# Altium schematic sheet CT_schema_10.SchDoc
size 387 x 385 mm
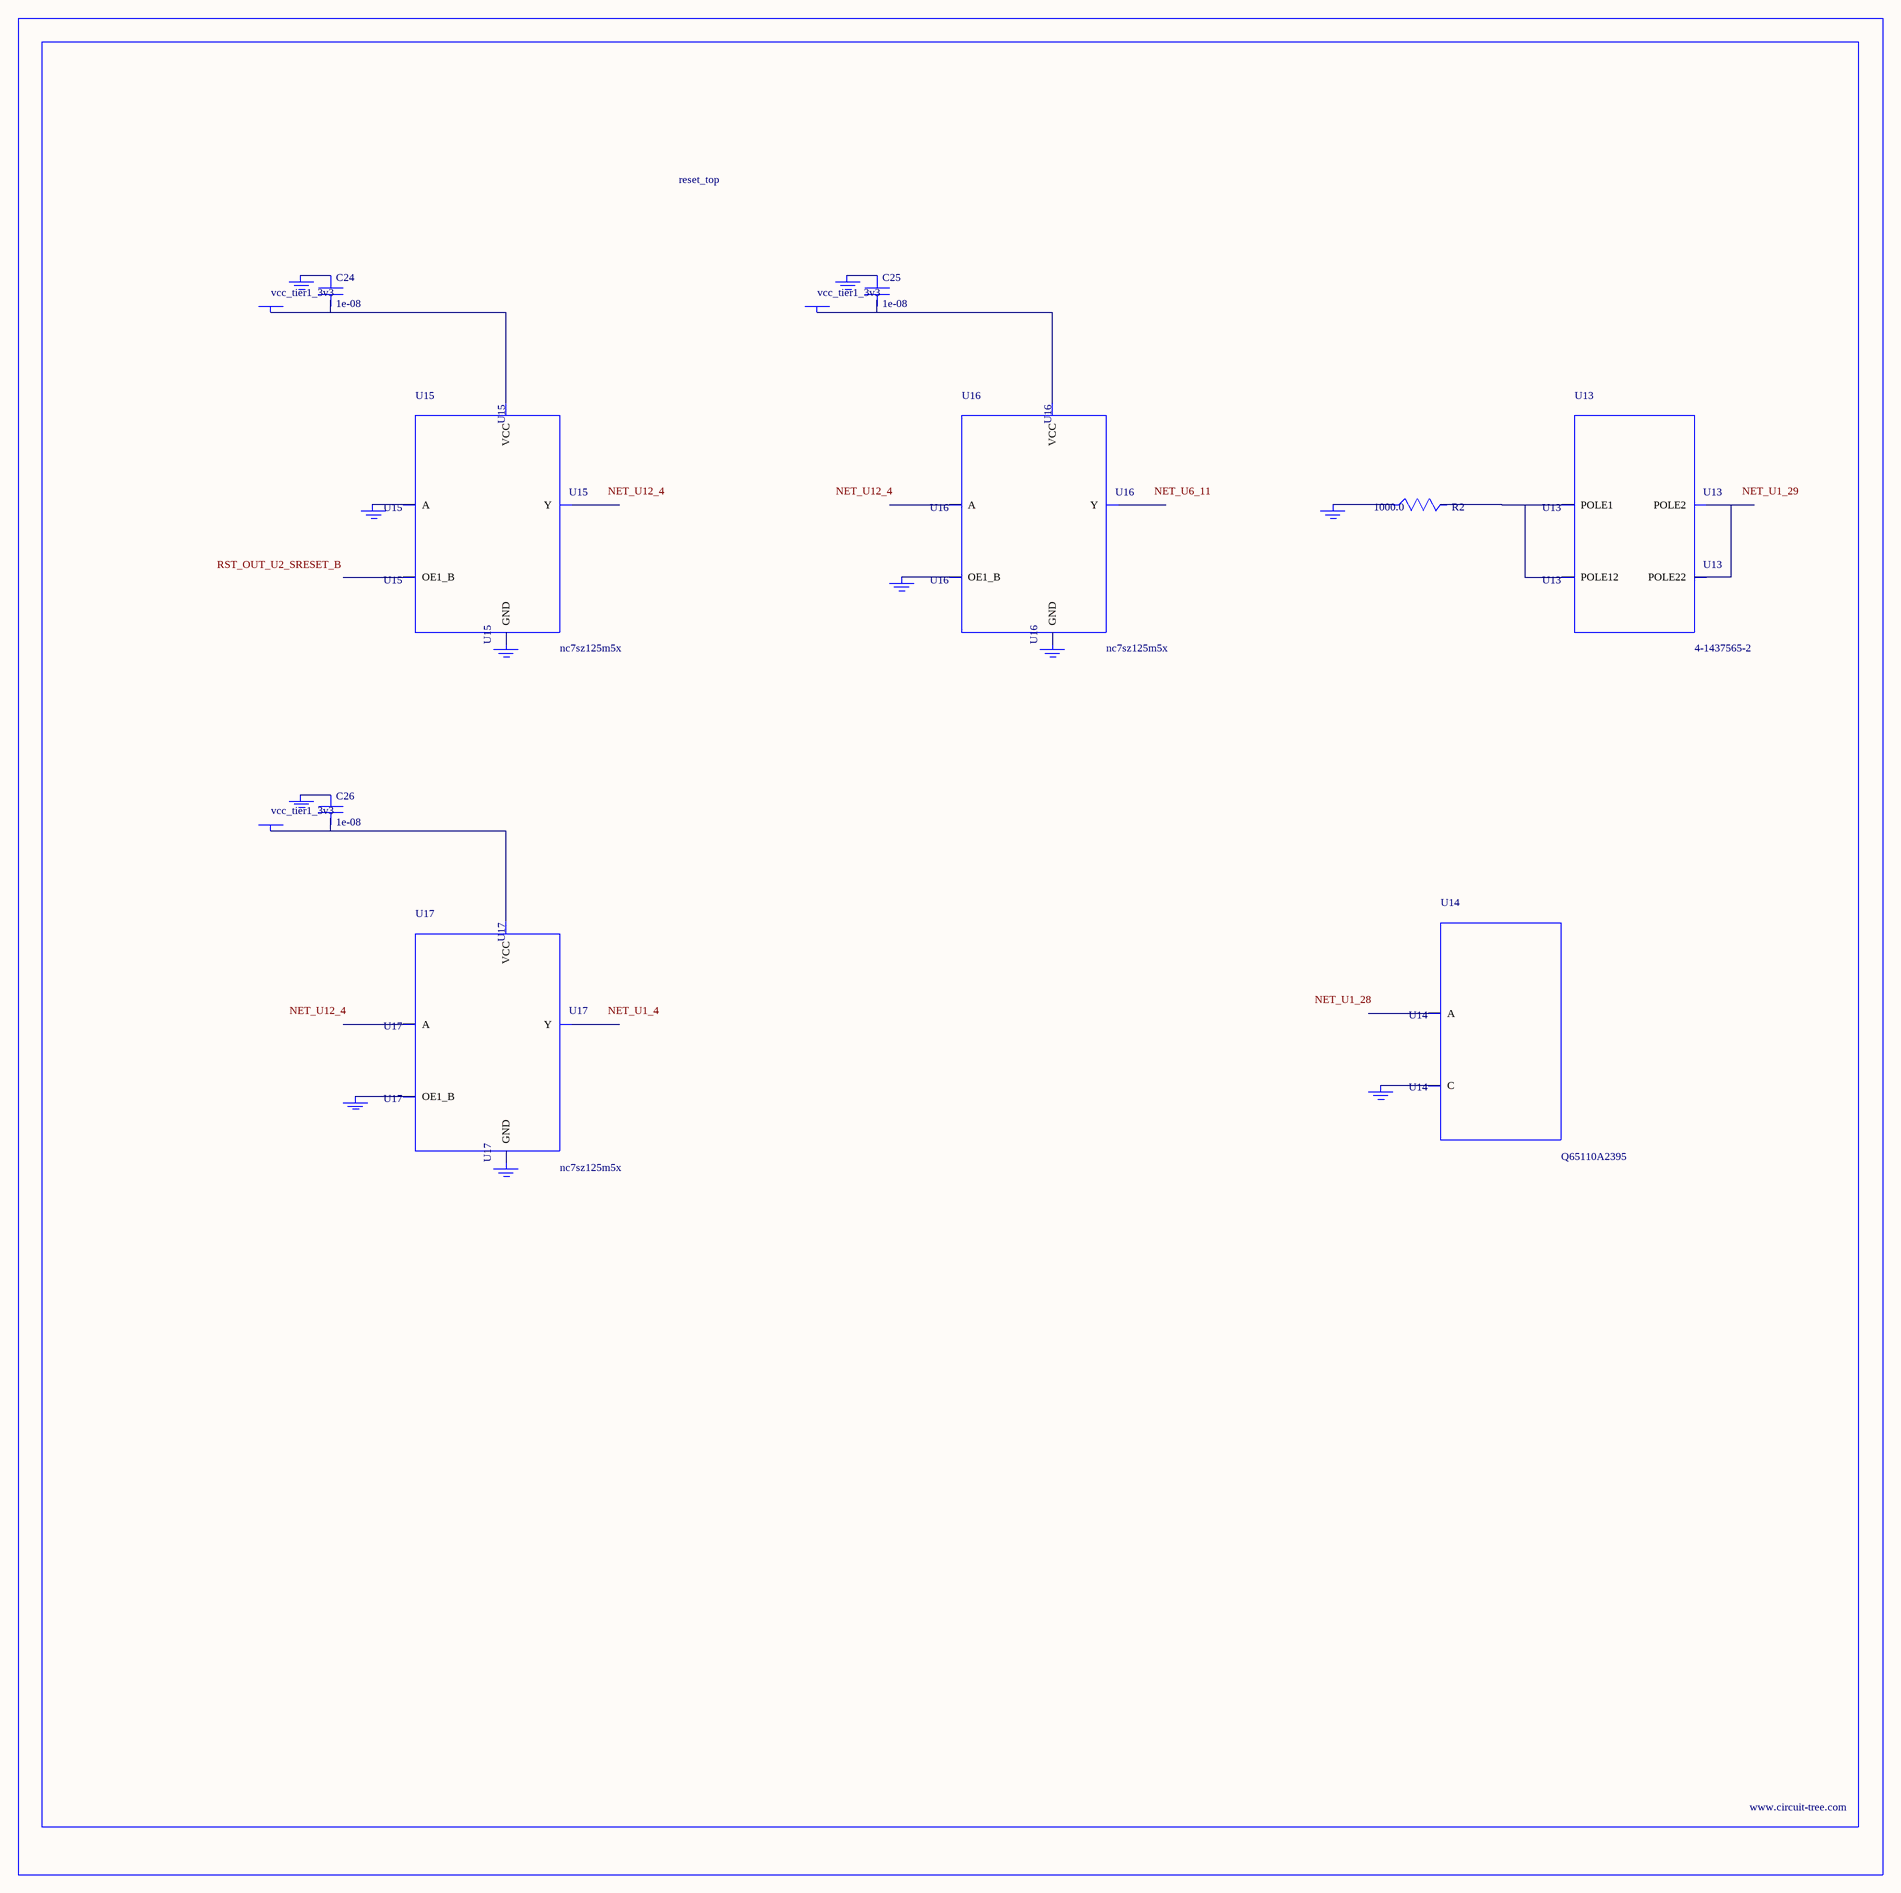
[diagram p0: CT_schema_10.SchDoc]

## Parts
BORDER9  (no value)
C24  1e-08  [C0402]
C25  1e-08  [C0402]
C26  1e-08  [C0402]
GND_INSTANCE_9_0  (no value)
GND_INSTANCE_9_1  (no value)
GND_INSTANCE_9_2  (no value)
GND_INSTANCE_9_3  (no value)
GND_INSTANCE_9_4  (no value)
GND_INSTANCE_9_5  (no value)
GND_INSTANCE_9_6  (no value)
GND_INSTANCE_9_7  (no value)
GND_INSTANCE_9_8  (no value)
GND_INSTANCE_9_9  (no value)
GND_INSTANCE_9_10  (no value)
POWER_INSTANCE_9_0  vcc_tier1_3v3
POWER_INSTANCE_9_1  vcc_tier1_3v3
POWER_INSTANCE_9_2  vcc_tier1_3v3
R2  1000.0  [R0603]
U13  4-1437565-2  [SW_4-1437565-2]
U14  Q65110A2395  [LGM67K-G1J2-24-Z]
U15  nc7sz125m5x  [NC7SZ125M5X]
U16  nc7sz125m5x  [NC7SZ125M5X]
U17  nc7sz125m5x  [NC7SZ125M5X]

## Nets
NetC24_1: C24.1 GND_INSTANCE_9_2.0(GND)
NetC24_2: C24.2 POWER_INSTANCE_9_0.0(PWR) U15.5(VCC)
NetC25_1: C25.1 GND_INSTANCE_9_5.0(GND)
NetC25_2: C25.2 POWER_INSTANCE_9_1.0(PWR) U16.5(VCC)
NetC26_1: C26.1 GND_INSTANCE_9_8.0(GND)
NetC26_2: C26.2 POWER_INSTANCE_9_2.0(PWR) U17.5(VCC)
NetGND_INSTANCE_9_0_0: GND_INSTANCE_9_0.0(GND) R2.1
NetGND_INSTANCE_9_1_0: GND_INSTANCE_9_1.0(GND) U14.C
NetGND_INSTANCE_9_3_0: GND_INSTANCE_9_3.0(GND) U15.2(A)
NetGND_INSTANCE_9_4_0: GND_INSTANCE_9_4.0(GND) U15.3(GND)
NetGND_INSTANCE_9_6_0: GND_INSTANCE_9_6.0(GND) U16.1(OE1_B)
NetGND_INSTANCE_9_7_0: GND_INSTANCE_9_7.0(GND) U16.3(GND)
NetGND_INSTANCE_9_9_0: GND_INSTANCE_9_9.0(GND) U17.1(OE1_B)
NetGND_INSTANCE_9_10_0: GND_INSTANCE_9_10.0(GND) U17.3(GND)
NetR2_2: R2.2 U13.1(POLE1) U13.2(POLE12)
NetU13_3: U13.3(POLE2) U13.4(POLE22)

Not connected (* = marked no-connect by the designer): U14 A; U15 1(OE1_B) 4(Y); U16 2(A) 4(Y); U17 2(A) 4(Y)

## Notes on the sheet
- Labels drawn without touching a wire or pin: NET_U1_4, NET_U1_28, NET_U1_29, NET_U6_11, NET_U12_4, RST_OUT_U2_SRESET_B

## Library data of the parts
BORDER9 = BORDER_PAGE9
C24-C26 = C0402C103K3RAC
GND_INSTANCE_9_0-GND_INSTANCE_9_10 = GND
POWER_INSTANCE_9_0-POWER_INSTANCE_9_2 = PWR
R2 = RC0603JR-071KL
